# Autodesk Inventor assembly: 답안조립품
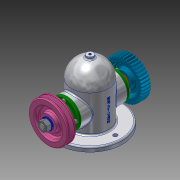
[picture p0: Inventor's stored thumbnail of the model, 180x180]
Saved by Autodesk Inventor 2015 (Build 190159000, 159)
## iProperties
Created: 2019-11
Part Number: 답안조립품
Document SubType Name: Assembly
Designer: LINEART-SSD.D4.16.04
Author: LINEART-SSD.D4.16.04
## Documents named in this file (14)
- C:\Users\LINEART-SSD.D4.16.04\Desktop\491104V1015\답안조립품.iam
- C:\Users\LINEART-SSD.D4.16.04\Desktop\491104V1015\본체.ipt
- C:\Users\LINEART-SSD.D4.16.04\Desktop\491104V1015\491104V1015\베어링 6203.ipt
- C:\Users\LINEART-SSD.D4.16.04\Desktop\491104V1015\491104V1015\축.ipt
- C:\Users\LINEART-SSD.D4.16.04\Desktop\491104V1015\491104V1015\부시.ipt
- C:\Users\LINEART-SSD.D4.16.04\Desktop\491104V1015\491104V1015\커버.ipt
- C:\Users\LINEART-SSD.D4.16.04\Desktop\491104V1015\491104V1015\오일 실 26 38 8.ipt
- C:\Users\LINEART-SSD.D4.16.04\Desktop\491104V1015\491104V1015\볼트 M4.ipt
- C:\Users\LINEART-SSD.D4.16.04\Desktop\491104V1015\491104V1015\키 5x5x12.ipt
- C:\Users\LINEART-SSD.D4.16.04\Desktop\491104V1015\491104V1015\V-벨트풀리.ipt
- V-벨트풀리.ipt
- C:\Users\LINEART-SSD.D4.16.04\Desktop\491104V1015\491104V1015\스퍼기어.ipt
- C:\Users\LINEART-SSD.D4.16.04\Desktop\491104V1015\491104V1015\와셔 12x24.ipt
- C:\Users\LINEART-SSD.D4.16.04\Desktop\491104V1015\491104V1015\너트 M12x1.25.ipt
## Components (1 placed, 1 different names)
1. V-벨트풀리:1 — 각도:3
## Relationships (1: Angle 1)
- 각도:3 [Angle]: V-벨트풀리:1
